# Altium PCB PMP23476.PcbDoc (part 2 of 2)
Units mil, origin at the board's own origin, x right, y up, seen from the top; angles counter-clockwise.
Board outline 965 x 1259.84 mil, 4 copper layers (Top Layer, Signal Layer 1, Signal Layer 2, Bottom Layer), stack 62 mil thick; 45 components, 25 nets, 111 pads, 20 vias.
Unrouted connection lines stored in the file: 2.
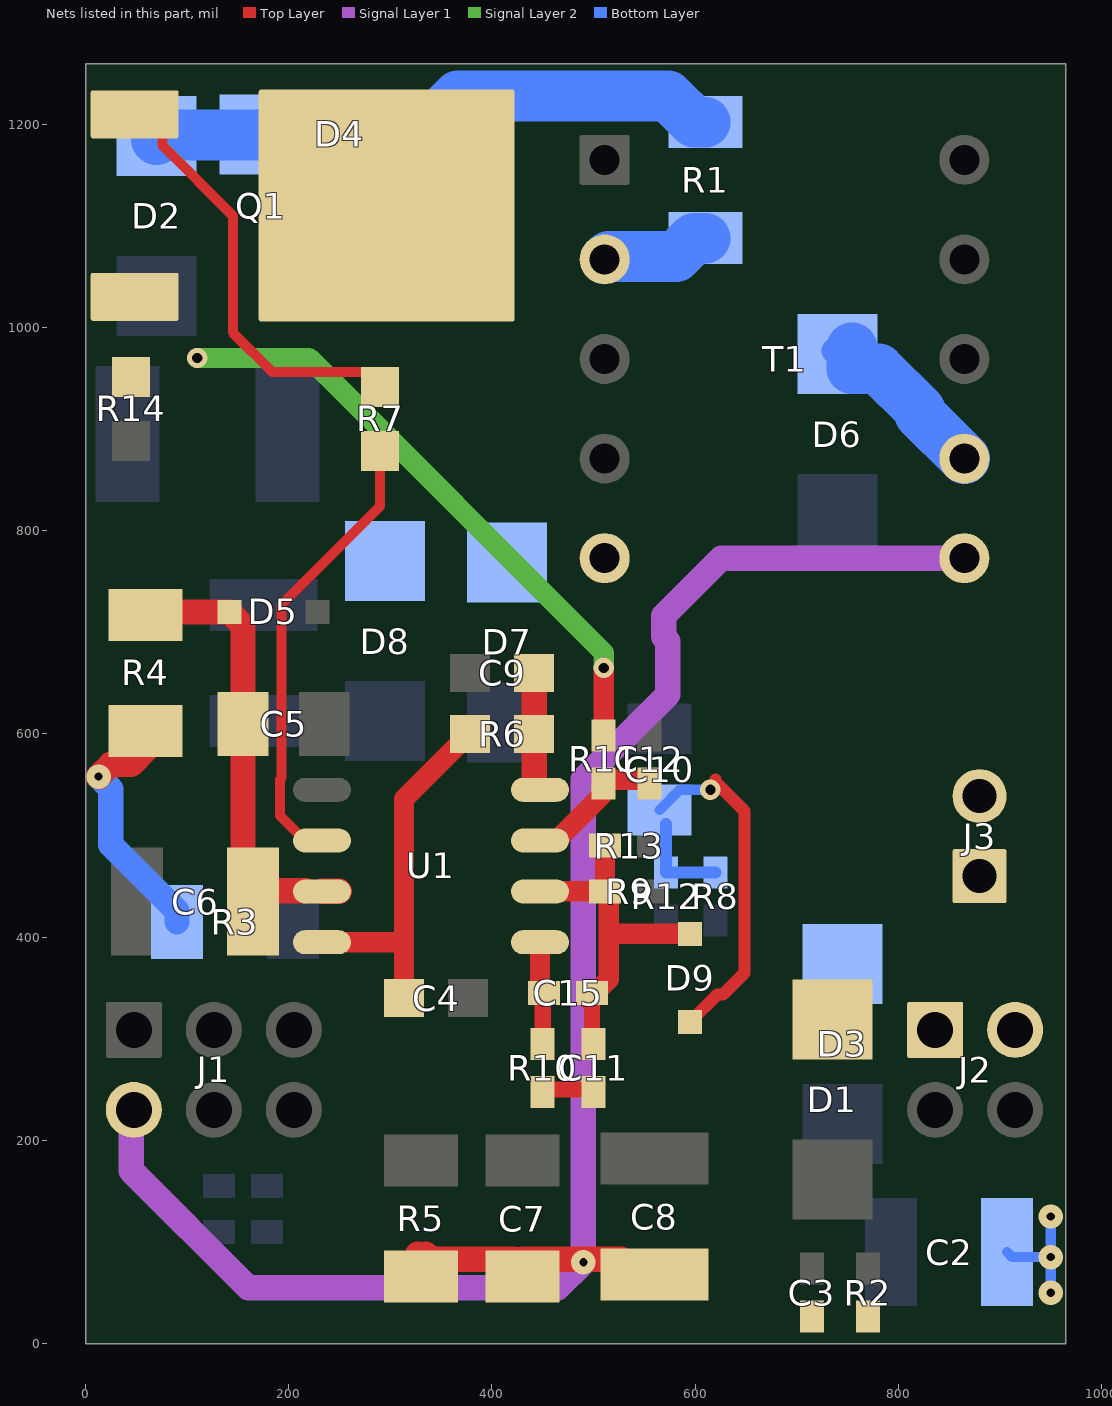
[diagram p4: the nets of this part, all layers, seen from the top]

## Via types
v1: diameter 24, hole 8, Top Layer to Bottom Layer, tented both sides, 12 vias
v2: diameter 20, hole 10, Top Layer to Bottom Layer, 8 vias

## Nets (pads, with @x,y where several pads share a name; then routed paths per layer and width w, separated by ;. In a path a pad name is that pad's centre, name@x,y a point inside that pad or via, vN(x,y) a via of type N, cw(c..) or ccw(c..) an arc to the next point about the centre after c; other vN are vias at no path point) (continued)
HSS: C7.2 C8.1 J1.2 R5.1 T1.6 | length 1788.8
  Top Layer w25: J1.2@45,230 J1.2@53.28,221.72 ; R5.1@327.09,87.91 R5.1@332.09,82.91 ; R5.1@330,82.91 R5.1@332.09,82.91 ; R5.1@335,80 R5.1@332.09,82.91 ; R5.1@335,87.91 R5.1@340,82.91 ; R5.1@348.09,74.82 R5.1@340,82.91 ; C7.2@425,80 422.09,82.91 R5.1@340,82.91 ; C7.2@430,82.91 527.09,82.91 C8.1@530,80 ; R5.1@332.09,82.91 R5.1@340,82.91
  Signal Layer 1 w25: J1.2@45,230 45,170 160,55 465,55 v1(490,80) ; v1@490,85 490,555.55 573.25,638.8 573.25,691.2 568.99,695.46 568.99,716.17 625.82,773 T1.6@865,773
NetC4_1: C4.1 R6.2 U1.8 | length 365.5
  Top Layer w20: U1.8@230,395 U1.8@232.72,395 310,395 ; C4.1@313.5,340 313.5,535.98 375,597.48 R6.2@375,600
NetC5_1: C5.1 C6.2 D5.1 R4.2 U1.7 | length 455
  Top Layer w25: R4.2@82.72,704 69.63,717.09 R4.2@58.8,717.09 61.71,720 D5.1@141.69,720 155,706.69 155,620 C5.1@160,615 ; C5.1@155,610 155,470 179.31,445.69 U1.7@216.67,445.69 ; U1.7@232.72,445 U1.7@250,445
NetC9_2: C9.2 R6.1 U1.4 | length 125.8
  Top Layer w25: U1.4@441.5,545.69 R6.1@441.5,605 ; C9.2@441.5,665 441.5,603.5 R6.1@445,600
NetC10_2: C10.2 D9.2 R8.1 R12.2 | length 430.2
  Top Layer w12: D9.2@595,316.69 621.96,343.65 627.41,343.65 648.56,364.8 648.56,524.18 620,552.74 620,555
  Bottom Layer w10: C10.2@565,525 585,545 v2(615,545)
  Bottom Layer w12: C10.2@571.46,511.46 R12.2@571.46,463.62 R8.1@620,463.62
NetC11_1: C11.1 R10.1 | length 50.9
  Top Layer w6: C11.1@497.76,250 C11.1@500,247.76
  Top Layer w16: R10.1@450,250 C11.1@497.76,250
NetC11_2: C11.2 C15.2 D9.1 R9.1 R13.2 U1.2 | length 357.7
  Top Layer w6: C11.2@498.62,296.38 C11.2@500,295 ; C15.2@498.62,344.37 C15.2@498.62,345
  Top Layer w16: C11.2@498.62,296.38 C15.2@498.62,344.37
  Top Layer w20: U1.2@447.28,445 R9.1@511.38,445 513.19,445 515,443.19 515,403.31 ; C15.2@495,338.62 495,342.56 496.81,344.37 498.62,344.37 500.75,344.37 515,358.62 515,403.31 ; R13.2@511.38,490 511.38,446.81 R9.1@511.59,446.59 ; D9.1@595,403.31 515,403.31
NetC12_1: C12.1 R11.1 U1.3 | length 125.5
  Top Layer w20: U1.3@447.28,495 463.54,495 508.19,539.65 R11.1@508.19,548.19 ; R11.1@520,555 553.19,555 555,553.19 C12.1@555,551.38
NetC15_1: C15.1 R10.2 U1.1 | length 100
  Top Layer w16: R10.2@450,295 C15.1@450,345
  Top Layer w20: C15.1@447.28,345 U1.1@447.28,395
NetD1_2: D1.2 D3.2 J3.1
NetD2_1: D2.1 D4.1 | length 103.3
  Bottom Layer w50: D2.1@70,1185 74.37,1189.37 170.63,1189.37 D4.1@171.26,1190
NetD4_2: D4.2 R1.1 | length 318.9
  Bottom Layer w20: D4.2@328.74,1190 335,1196.26 D4.2@358.74,1220
  Bottom Layer w50: D4.2@335,1185 D4.2@335,1196.26 ; D4.2@358.74,1220 366.61,1227.87 573.39,1227.87 599.17,1202.09 R1.1@610,1202.09
NetD6_2: D6.2 T1.7 | length 179.1
  Bottom Layer w25: D6.2@736.74,977 D6.2@740,973.74 ; D6.2@745,970 D6.2@748,973
  Bottom Layer w50: D6.2@754.37,980 754.37,959.37 780.63,959.37 821.36,918.64 821.36,914.64 T1.7@865,871
NetD7_2: D7.2 D8.2 T1.5
NetQ1_1: Q1.1 R7.2 | length 414.2
  Top Layer w10: Q1.1@65,1208.31 75.87,1197.43 75.87,1179.13 145,1110 145,995 183.82,956.18 276.3,956.18 290,942.48 R7.2@290,941.5
NetQ1_3: Q1.3 R11.2 R14.2 | length 601.5
  Top Layer w20: R11.2@510,598.62 v2(510,665)
  Signal Layer 2 w20: v2(110,970) 220,970 510,680 v2(510,665)
NetQ1_4: Q1.4 R1.2 T1.2 | length 102.4
  Bottom Layer w50: T1.2@515,1070 581.26,1070 599.17,1087.91 R1.2@610,1087.91
NetR3_2: R3.2 R4.1 | length 233.1
  Top Layer w25: v1(12.92,557.92) 25,570 45,570 R4.1@60,585
  Bottom Layer w25: v1(12.92,557.92) 25,545.83 25,490.83 90,425.83 R3.2@90,415
NetR7_1: R7.1 U1.6 | length 432.8
  Top Layer w10: U1.6@232.72,495 215.98,495 191.3,519.68 191.3,555.22 192.87,556.8 192.87,727.13 290,824.25 R7.1@290,860
SGND: C2.2 C3.2 J2.1 J2.3 J3.2 R2.1 | length 120
  Bottom Layer w10: C2.2@907.09,90 912.09,85 v1(950,85) ; v1(950,50) v1(950,85) ; v1(950,125) v1(950,85)
pads on no net: T1.3 T1.8 T1.9 T1.10
copper on no net: | length 121162.2
  Top Layer w1: 3666.62,2042.82 3766.3,2142.5 3886.3,2262.5 4006.3,2382.5 4126.3,2502.5 4246.3,2622.5 4366.3,2742.5 4486.3,2862.5 4606.3,2982.5 4726.3,3102.5 4786.3,3162.5 ; 3666.62,2102.82 3706.3,2142.5 3826.3,2262.5 3946.3,2382.5 4066.3,2502.5 4186.3,2622.5 4306.3,2742.5 4426.3,2862.5 4546.3,2982.5 4666.3,3102.5 4786.3,3222.5 ; 3666.62,2162.82 3766.3,2262.5 3886.3,2382.5 4006.3,2502.5 4126.3,2622.5 4246.3,2742.5 4366.3,2862.5 4486.3,2982.5 4606.3,3102.5 4726.3,3222.5 4786.3,3282.5 ; 3666.62,2222.82 3706.3,2262.5 3826.3,2382.5 3946.3,2502.5 4066.3,2622.5 4186.3,2742.5 4306.3,2862.5 4426.3,2982.5 4546.3,3102.5 4666.3,3222.5 4786.3,3342.5 ; 3666.62,2282.82 3766.3,2382.5 3886.3,2502.5 4006.3,2622.5 4126.3,2742.5 4246.3,2862.5 4366.3,2982.5 4486.3,3102.5 4606.3,3222.5 4726.3,3342.5 4786.3,3402.5 ; 3666.62,2342.82 3706.3,2382.5 3826.3,2502.5 3946.3,2622.5 4066.3,2742.5 4186.3,2862.5 4306.3,2982.5 4426.3,3102.5 4546.3,3222.5 4666.3,3342.5 4786.3,3462.5 ; 3666.62,2402.82 3766.3,2502.5 3886.3,2622.5 4006.3,2742.5 4126.3,2862.5 4246.3,2982.5 4366.3,3102.5 4486.3,3222.5 4606.3,3342.5 4726.3,3462.5 4786.3,3522.5 ; 3666.62,2462.82 3706.3,2502.5 3826.3,2622.5 3946.3,2742.5 4066.3,2862.5 4186.3,2982.5 4306.3,3102.5 4426.3,3222.5 4546.3,3342.5 4666.3,3462.5 4786.3,3582.5 ; 3666.62,2522.82 3766.3,2622.5 3886.3,2742.5 4006.3,2862.5 4126.3,2982.5 4246.3,3102.5 4366.3,3222.5 4486.3,3342.5 4606.3,3462.5 4726.3,3582.5 ; 3666.62,2582.82 3706.3,2622.5 3826.3,2742.5 3946.3,2862.5 4066.3,2982.5 4186.3,3102.5 4306.3,3222.5 4426.3,3342.5 4546.3,3462.5 4666.3,3582.5 ; 3666.62,2642.82 3766.3,2742.5 3886.3,2862.5 4006.3,2982.5 4126.3,3102.5 4246.3,3222.5 4366.3,3342.5 4486.3,3462.5 4606.3,3582.5 ; 3666.62,2702.82 3706.3,2742.5 3826.3,2862.5 3946.3,2982.5 4066.3,3102.5 4186.3,3222.5 4306.3,3342.5 4426.3,3462.5 4546.3,3582.5 ; 3666.62,2762.82 3766.3,2862.5 3886.3,2982.5 4006.3,3102.5 4126.3,3222.5 4246.3,3342.5 4366.3,3462.5 4486.3,3582.5 ; 3666.62,2822.82 3706.3,2862.5 3826.3,2982.5 3946.3,3102.5 4066.3,3222.5 4186.3,3342.5 4306.3,3462.5 4426.3,3582.5 ; 3666.62,2882.82 3766.3,2982.5 3886.3,3102.5 4006.3,3222.5 4126.3,3342.5 4246.3,3462.5 4366.3,3582.5 ; 3666.62,2942.82 3706.3,2982.5 3826.3,3102.5 3946.3,3222.5 4066.3,3342.5 4186.3,3462.5 4306.3,3582.5 ; 3666.62,3002.82 3766.3,3102.5 3886.3,3222.5 4006.3,3342.5 4126.3,3462.5 4246.3,3582.5 ; 3666.62,3062.82 3706.3,3102.5 3826.3,3222.5 3946.3,3342.5 4066.3,3462.5 4186.3,3582.5 ; 3666.62,3122.82 3766.3,3222.5 3886.3,3342.5 4006.3,3462.5 4126.3,3582.5 ; 3666.62,3182.82 3706.3,3222.5 3826.3,3342.5 3946.3,3462.5 4066.3,3582.5 ; 3666.62,3242.82 3766.3,3342.5 3886.3,3462.5 4006.3,3582.5 ; 3666.62,3302.82 3706.3,3342.5 3826.3,3462.5 3946.3,3582.5 ; 3666.62,3362.82 3766.3,3462.5 3886.3,3582.5 ; 3666.62,3422.82 3706.3,3462.5 3826.3,3582.5 ; 3666.62,3482.82 3766.3,3582.5 ; 3666.62,3542.82 3706.3,3582.5 ; 3706.3,2022.5 3826.3,2142.5 3946.3,2262.5 4066.3,2382.5 4186.3,2502.5 4306.3,2622.5 4426.3,2742.5 4546.3,2862.5 4666.3,2982.5 4786.3,3102.5 ; 3766.3,2022.5 3886.3,2142.5 4006.3,2262.5 4126.3,2382.5 4246.3,2502.5 4366.3,2622.5 4486.3,2742.5 4606.3,2862.5 4726.3,2982.5 4786.3,3042.5 ; 3826.3,2022.5 3946.3,2142.5 4066.3,2262.5 4186.3,2382.5 4306.3,2502.5 4426.3,2622.5 4546.3,2742.5 4666.3,2862.5 4786.3,2982.5 ; 3886.3,2022.5 4006.3,2142.5 4126.3,2262.5 4246.3,2382.5 4366.3,2502.5 4486.3,2622.5 4606.3,2742.5 4726.3,2862.5 4786.3,2922.5 ; 3946.3,2022.5 4066.3,2142.5 4186.3,2262.5 4306.3,2382.5 4426.3,2502.5 4546.3,2622.5 4666.3,2742.5 4786.3,2862.5 ; 4006.3,2022.5 4126.3,2142.5 4246.3,2262.5 4366.3,2382.5 4486.3,2502.5 4606.3,2622.5 4726.3,2742.5 4786.3,2802.5 ; 4066.3,2022.5 4186.3,2142.5 4306.3,2262.5 4426.3,2382.5 4546.3,2502.5 4666.3,2622.5 4786.3,2742.5 ; 4126.3,2022.5 4246.3,2142.5 4366.3,2262.5 4486.3,2382.5 4606.3,2502.5 4726.3,2622.5 4786.3,2682.5 ; 4186.3,2022.5 4306.3,2142.5 4426.3,2262.5 4546.3,2382.5 4666.3,2502.5 4786.3,2622.5 ; 4246.3,2022.5 4366.3,2142.5 4486.3,2262.5 4606.3,2382.5 4726.3,2502.5 4786.3,2562.5 ; 4306.3,2022.5 4426.3,2142.5 4546.3,2262.5 4666.3,2382.5 4786.3,2502.5 ; 4366.3,2022.5 4486.3,2142.5 4606.3,2262.5 4726.3,2382.5 4786.3,2442.5 ; 4426.3,2022.5 4546.3,2142.5 4666.3,2262.5 4786.3,2382.5 ; 4486.3,2022.5 4606.3,2142.5 4726.3,2262.5 4786.3,2322.5 ; 4546.3,2022.5 4666.3,2142.5 4786.3,2262.5 ; 4606.3,2022.5 4726.3,2142.5 4786.3,2202.5 ; 4666.3,2022.5 4786.3,2142.5 ; 4726.3,2022.5 4786.3,2082.5
  Top Layer w15: 237.5,2142.5 647.41,2142.5 1587.15,2142.5 2446.92,2142.5 3096.76,2142.5 3666.62,2142.5 4786.3,2142.5 ; 237.5,2262.5 647.41,2262.5 1587.15,2262.5 2446.92,2262.5 3096.76,2262.5 3666.62,2262.5 4786.3,2262.5 ; 237.5,2382.5 647.41,2382.5 1587.15,2382.5 2446.92,2382.5 3096.76,2382.5 3666.62,2382.5 4786.3,2382.5 ; 237.5,2502.5 647.41,2502.5 1587.15,2502.5 2446.92,2502.5 3096.76,2502.5 3666.62,2502.5 4786.3,2502.5 ; 237.5,2622.5 647.41,2622.5 1587.15,2622.5 2446.92,2622.5 3096.76,2622.5 3666.62,2622.5 4786.3,2622.5 ; 237.5,2742.5 647.41,2742.5 1587.15,2742.5 2446.92,2742.5 3096.76,2742.5 3666.62,2742.5 4786.3,2742.5 ; 237.5,2862.5 647.41,2862.5 1587.15,2862.5 2446.92,2862.5 3096.76,2862.5 3666.62,2862.5 4786.3,2862.5 ; 237.5,2982.5 647.41,2982.5 1587.15,2982.5 2446.92,2982.5 3096.76,2982.5 3666.62,2982.5 4786.3,2982.5 ; 237.5,3102.5 647.41,3102.5 1587.15,3102.5 2446.92,3102.5 3096.76,3102.5 3666.62,3102.5 4786.3,3102.5 ; 237.5,3222.5 647.41,3222.5 1587.15,3222.5 2446.92,3222.5 3096.76,3222.5 3666.62,3222.5 4786.3,3222.5 ; 237.5,3342.5 647.41,3342.5 1587.15,3342.5 2446.92,3342.5 3096.76,3342.5 3666.62,3342.5 4786.3,3342.5 ; 237.5,3462.5 647.41,3462.5 1587.15,3462.5 2446.92,3462.5 3096.76,3462.5 3666.62,3462.5 4786.3,3462.5 ; 237.5,3582.5 4786.3,3582.5 ; 647.41,3702.5 647.41,2022.5 ; 1587.15,3702.5 1587.15,2022.5 ; 2446.92,3702.5 2446.92,2022.5 ; 3096.76,3702.5 3096.76,2022.5 ; 3666.62,3702.5 3666.62,2022.5 ; 647.41,2022.5 237.5,2022.5 237.5,3702.5 4786.3,3702.5 4786.3,2022.5 3666.62,2022.5 ; 647.41,2022.5 1587.15,2022.5 ; 1587.15,2022.5 2446.92,2022.5 ; 2446.92,2022.5 3096.76,2022.5 ; 3096.76,2022.5 3666.62,2022.5

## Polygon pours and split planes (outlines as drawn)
GND_PRI on Signal Layer 1 "SIGNAL_LAYER_1_GND_PRI_P108" (solid, remove dead copper, pour order 108): 5,1005 605,1005 655,955 655,295 360,0 0,0
SGND on Signal Layer 1 "SIGNAL_LAYER_1_SGND_P098" (solid, remove dead copper, pour order 98): 690,695 690,0 965,0 965,695
GND_PRI on Signal Layer 2 "SIGNAL_LAYER_2_GND_PRI_P111" (solid, remove dead copper, pour order 111): 275,831.62 275,165 545,165 660,280 660,581.62
GND_PRI on Signal Layer 2 "SIGNAL_LAYER_2_GND_PRI_P110" (solid, remove dead copper, pour order 110): 595,900 655,840 655,505 600,505 330,775 220,775 220,885 235,900
GND_PRI on Signal Layer 2 "SIGNAL_LAYER_2_GND_PRI_P109" (solid, remove dead copper, pour order 109): 0,950 210,950 265,895 265,165 0,165
SGND on Signal Layer 2 "SIGNAL_LAYER_2_SGND_P099" (solid, remove dead copper, pour order 99): 690,695 690,0 965,0 965,695
NetQ1_4 on Top Layer "TOP_LAYER_NETQ1_4_P105" (solid, remove dead copper, pour order 105): 165,1260 165,1005 175,995 510,995 555,1040 555,1105 535,1125 485,1125 465,1145 465,1260
GND_PRI on Top Layer "TOP_LAYER_GND_PRI_P104" (solid, remove dead copper, pour order 104): -5,1010 0,1005 600,1005 660,945 660,335 490,165 0.03,165
NetQ1_3 on Top Layer "TOP_LAYER_NETQ1_3_P100" (solid, remove dead copper, pour order 100): 0,1080 145,1080 145,945 120,920 0,920
SGND on Top Layer "TOP_LAYER_SGND_P094" (solid, remove dead copper, pour order 94): 690,695 690,0 965,0 965,695
NetD1_2 on Top Layer "TOP_LAYER_NETD1_2_P093" (solid, remove dead copper, pour order 93): 690,385 805,500 960,500 960,400 945,385 830,385 795,350 795,270 690,270
12Vs on Top Layer "TOP_LAYER_12VS_P091" (solid, remove dead copper, pour order 91): 690,60 695,55 860,55 860,155 880,175 965,175 965,265 810,265 800,255 800,200 785,185 695,185 690,180
GND_PRI on Bottom Layer "BOTTOM_LAYER_GND_PRI_P107" (solid, remove dead copper, pour order 107): 10,995 605,995 660,940 660,305 365,10 0,10
12Vp on Bottom Layer "BOTTOM_LAYER_12VP_P106" (solid, remove dead copper, pour order 106): 155,225 155,80 165,70 295,70 385,160 385,625 255,625 250,630 250,320
GND_PRI on Bottom Layer "BOTTOM_LAYER_GND_PRI_P103" (solid, remove dead copper, pour order 103): 95,700 110,685 230,685 250,705 250,970 225,995 120,995 95,970
12Vp on Bottom Layer "BOTTOM_LAYER_12VP_P102" (solid, remove dead copper, pour order 102): 115,575 130,560 555,560 570,575 630,575 645,590 645,645 630,660 125,660 120,655 115,655
NetD7_2 on Bottom Layer "BOTTOM_LAYER_NETD7_2_P101" (solid, remove dead copper, pour order 101): 250,815 540,815 565,790 565,725 545,705 265,705 250,720
SGND on Bottom Layer "BOTTOM_LAYER_SGND_P097" (solid, remove dead copper, pour order 97): 690,695 690,0 970,0 970,685 960,695
12Vs on Bottom Layer "BOTTOM_LAYER_12VS_P096" (solid, remove dead copper, pour order 96): 690,25 715,0 835,0 855,20 855,145 885,175 965,175 965,270 690,270
NetD1_2 on Bottom Layer "BOTTOM_LAYER_NETD1_2_P095" (solid, remove dead copper, pour order 95): 690,290 785,290 800,305 800,355 835,390 955,390 965,400 965,500 790,500 690,400

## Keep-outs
Keep-Out Layer:
  text ".Layer_Name" at 577,-858.49 h60

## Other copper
Top Layer:
  text "Layer" at 307.5,3612.5 h60
  text "Name" at 717.41,3612.5 h60
  text "Material" at 1657.15,3612.5 h60
  text "Thickness" at 2516.92,3612.5 h60
  text "Constant" at 3166.76,3612.5 h60
  text "Board Layer Stack" at 3736.62,3612.5 h60
  text "Top Overlay" at 717.41,3492.5 h60
  text "Top Solder" at 717.41,3372.5 h60
  text "Solder Resist" at 1657.15,3372.5 h60
  text "0.40mil" at 2516.92,3372.5 h60
  text "3.5" at 3166.76,3372.5 h60
  text "1" at 307.5,3252.5 h60
  text "Top Layer" at 717.41,3252.5 h60
  text "1.40mil" at 2516.92,3252.5 h60
  text "Dielectric 1" at 717.41,3132.5 h60
  text "8.00mil" at 2516.92,3132.5 h60
  text "4.2" at 3166.76,3132.5 h60
  text "Dielectric1" at 717.41,3012.5 h60
  text "8.00mil" at 2516.92,3012.5 h60
  text "4.2" at 3166.76,3012.5 h60
  text "2" at 307.5,2892.5 h60
  text "Signal Layer 1" at 717.41,2892.5 h60
  text "1.40mil" at 2516.92,2892.5 h60
  text "Dielectric 3" at 717.41,2772.5 h60
  text "FR-4" at 1657.15,2772.5 h60
  text "24.40mil" at 2516.92,2772.5 h60
  text "4.2" at 3166.76,2772.5 h60
  text "3" at 307.5,2652.5 h60
  text "Signal Layer 2" at 717.41,2652.5 h60
  text "1.40mil" at 2516.92,2652.5 h60
  text "Dielectric 2" at 717.41,2532.5 h60
  text "8.00mil" at 2516.92,2532.5 h60
  text "4.2" at 3166.76,2532.5 h60
  text "Dielectric 4" at 717.41,2412.5 h60
  text "8.00mil" at 2516.92,2412.5 h60
  text "4.2" at 3166.76,2412.5 h60
  text "4" at 307.5,2292.5 h60
  text "Bottom Layer" at 717.41,2292.5 h60
  text "1.40mil" at 2516.92,2292.5 h60
  text "Bottom Solder" at 717.41,2172.5 h60
  text "Solder Resist" at 1657.15,2172.5 h60
  text "0.40mil" at 2516.92,2172.5 h60
  text "3.5" at 3166.76,2172.5 h60
  text "Bottom Overlay" at 717.41,2052.5 h60
  text ".Layer_Name" at 577,-858.49 h60
Bottom Layer:
  text ".Layer_Name" at 577,-858.49 h60

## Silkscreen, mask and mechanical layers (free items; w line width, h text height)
Top Overlay:
  lines w10: 285,725 285,840 355,840 430,765 430,695 350,695 330,715 295,715 285,725
  text ".Layer_Name" at 577,-858.49 h60
Bottom Overlay:
  text "'.PRJ_Number'.PCB_Rev-" at 635,20 h60
  text ".Layer_Name" at 577,-858.49 h60
Top Paste:
  text ".Layer_Name" at 577,-858.49 h60
Bottom Paste:
  text ".Layer_Name" at 577,-858.49 h60
Top Solder:
  text ".Layer_Name" at 577,-858.49 h60
  text ".Layer_Name" at 577,-858.49 h60
Bottom Solder:
  text ".Layer_Name" at 577,-858.49 h60
Drill Guide:
  text ".Layer_Name" at 577,-858.49 h60
M1 Board Outline:
  lines w7: 0,0 0,1262.95 ; 0,1259.84 964.57,1259.84
  lines w10: 0,0 969.57,0 ; 964.57,1259.84 965,0
  text ".Layer_Name" at 577,-858.49 h60
M2 Board Dimensions:
  rectangle: 0,-275 125,-150
  rectangle: 125,-400 500,-275
  lines w7: 0,-275 1000,-275 ; 125,-400 125,-150 ; 250,-400 250,-150 ; 500,-400 500,-150 ; 750,-400 750,-150 ; 0,-400 1000,-400 1000,-150 0,-150 0,-400
  text ".Layer_Name" at 577,-858.49 h60
M3 3D STEP Top:
  text ".Layer_Name" at 577,-858.49 h60
M4 3D STEP Bottom:
  text ".Layer_Name" at 577,-858.49 h60
M5 Assembly Top:
  lines w10: -292,-930.17 6308,-930.17 ; -292,-726.83 6310,-726.83 ; -292,-523.5 -292,-1133.5 3713,-1133.5 6310,-1133.5 6310,-523.5 -291.5,-523.5 -291.5,-1133.5 1284,-1133.5 ; 2173,-1133.5 2173,-523.5 ; 3440,-726.83 3440,-523.5 ; 4280,-726.83 4280,-523.5 ; 4902,-1140 4902,-937.17
  text "COMPONENTS MARKED 'DNP' SHOULD NOT BE POPULATED." at 1153.5,-318.5 h60
  text "ASSEMBLY VARIANT:" at 1153,-434 h60
  text ".VariantName" at 2189,-434 h60
  text "PCB VIEWED FROM TOP SIDE" at -228.5,-655.67 h60
  text "BOARD #:" at 2248,-655.67 h60
  text ".PRJ_Number" at 2793.5,-655.67 h60
  text "REV:" at 3638,-655.67 h60
  text ".PCB_Rev" at 3929.5,-655.67 h60
  text "SVN REV:" at 4476,-655.67 h60
  text ".VersionControl_RevNumber" at 4982,-655.67 h60
  text "TID #:" at 2248,-859 h60
  text ".TID" at 2793.5,-859 h60
  text "PLOT NAME =" at -228.5,-1064.34 h60
  text ".plot_File_Name" at 577,-1064.34 h60
  text "GENERATED    :" at 2250,-1064.34 h60
  text ".Print_Date" at 3119.5,-1064.34 h60
  text ".Print_Time" at 3848.5,-1064.34 h60
  text "TEXAS INSTRUMENTS" at 5113,-1064.34 h60
M6 Assembly Bottom:
  lines w10: -292.5,-727.33 6309.5,-727.33 ; -290.5,-930.67 6309.5,-930.67 ; 1115.5,-1140.5 1115.5,-937.67 ; 1737.5,-727.33 1737.5,-524 ; 2577.5,-727.33 2577.5,-524 ; 3844.5,-1134 3844.5,-524 ; 4733.5,-1134 6309,-1134 6309,-524 -292.5,-524 -292.5,-1134 2304.5,-1134 6309.5,-1134 6309.5,-524
  text "COMPONENTS MARKED 'DNP' SHOULD NOT BE POPULATED." at 6102,-318 h60
  text ".VariantName" at 5058,-434 h60
  text "ASSEMBLY VARIANT:" at 6097,-434 h60
  text ".VersionControl_RevNumber" at 1035.5,-656.17 h60
  text "SVN REV:" at 1541.5,-656.17 h60
  text ".PCB_Rev" at 2088,-656.17 h60
  text "REV:" at 2379.5,-656.17 h60
  text ".PRJ_Number" at 3224,-656.17 h60
  text "BOARD #:" at 3769.5,-656.17 h60
  text "PCB VIEWED FROM BOTTOM SIDE" at 6246,-656.17 h60
  text ".TID" at 3224,-859.5 h60
  text "TID #:" at 3769.5,-859.5 h60
  text "TEXAS INSTRUMENTS" at 904.5,-1064.84 h60
  text ".Print_Time" at 2169,-1064.84 h60
  text ".Print_Date" at 2898,-1064.84 h60
  text "GENERATED    :" at 3767.5,-1064.84 h60
  text ".plot_File_Name" at 5440.5,-1064.84 h60
  text "PLOT NAME =" at 6246,-1064.84 h60
M9 Title Sheet:
  drawing of 57 lines, arcs and shapes, not listed
  text "1" at 739.84,8036.5 h70
  text "2" at 3235.5,8036.5 h70
  text "3" at 5724.84,8036.5 h70
  text "4" at 8231.51,8036.5 h70
  text "5" at 10730.5,8036.5 h70
  text "6" at 13235.5,8036.5 h70
  text "A" at -416.5,6893.5 h70
  text "A" at 14383.5,6893.5 h70
  text "B" at -416.5,4513.5 h70
  text "B" at 14383.5,4513.5 h70
  text "C" at -416.5,2138.5 h70
  text "C" at 14383.5,2138.5 h70
  text "PROJECT TITLE:" at 11343.5,277.5 h45
  text ".PRJ_Title" at 11393.5,144.17 h70
  text "DESIGNED FOR:" at 11343.5,-23.5 h45
  text ".PRJ_Customer" at 11393.5,-163.5 h70
  text "D" at -416.5,-231.5 h70
  text "D" at 14383.5,-231.5 h70
  text "FILE NAME:" at 11343.5,-323.5 h45
  text ".PCB_File_Name_No_Path" at 11393.5,-443.5 h70
  text "Texas Instruments (TI) and/or its licensors do not warrant the accuracy or completeness of this specification" at 6374,-605.34 h45
  text "ENGINEER:" at 11343.5,-613.5 h45
  text "LAYOUT BY:" at 12848.5,-613.5 h45
  text "or any information contained therein. TI and/or its licensors do not warrant that this design will meet" at 6329.01,-718 h45
  text ".PRJ_Engineer" at 11393.5,-768.49 h70
  text ".PCB_Layout" at 12899,-768.49 h70
  text "the specifications, will be suitable for your application or fit for any particular purpose, or will operate in" at 6329.01,-830.67 h45
  text ".Layer_Name" at 577,-858.49 h60
  text "ALTIUM DESIGNER VERSION:" at 12848.5,-923.5 h45
  text "an implementation. TI and/or its licensors do not warrant that the design is production worthy. You should" at 6329.01,-943.33 h45
  text "completely validate and test your design implementation to confirm the system functionality for your application." at 6374,-1056 h45
  text ".print_Scale" at 11393.5,-1056.83 h70
  text ".Application_BuildNumber" at 12899,-1056.83 h70
  text "1" at 739.84,-1263.5 h70
  text "2" at 3235.5,-1263.5 h70
  text "3" at 5724.84,-1263.5 h70
  text "4" at 8231.51,-1263.5 h70
  text "5" at 10730.5,-1263.5 h70
  text "6" at 13235.5,-1263.5 h70
M10 Fab Notes:
  drawing of 173 lines, arcs and shapes, not listed
  text "DESIGN INFORMATION" at 12378.02,6201 h60
  text "MIN. TRACK WIDTH:" at 11733.46,6021 h60
  text "10" at 12829.7,6021 h60
  text "MIL" at 12984.46,6021 h60
  text "MIN. CLEARANCE:" at 11733.46,5889 h60
  text "0.2" at 12769.7,5889 h60
  text "mm" at 12984.46,5889 h60
  text "MIN. VIA PAD SIZE:" at 11733.46,5757 h60
  text "20" at 12799.71,5757 h60
  text "MIL" at 12984.46,5757 h60
  text "0.05mm (2MIL)" at 12428.46,5615.29 h60
  text "MINIMUM ANNULAR RING" at 11404.23,5611 h60
  text "EXTERNAL" at 13136.46,5611 h60
  text "PER" at 11604.23,5493 h60
  text "IPC-D-275 CLASS 2 LEVEL C" at 11824.23,5493 h60
  text "MIL, HOLES" at 13312.46,5380.71 h60
  text "+/-" at 12920,5380 h60
  text "+/-" at 13774,5380 h60
  text "REGISTRATION TOLERANCES:" at 11404.23,5375 h60
  text "METAL" at 12604,5375 h60
  text "5" at 13180.2,5375 h60
  text "3" at 14013.2,5375 h60
  text "MIL" at 14129.46,5375 h60
  text "+/-" at 13774,5262 h60
  text "HOLE SIZE TOLERANCE (UNLESS OTHERWISE SPECIFIED):" at 11404.23,5257 h60
  text "3" at 14013.2,5257 h60
  text "MIL" at 14129.46,5257 h60
  text "MATERIAL:" at 11329.46,5047.54 h60
  text "FR-4 High Tg" at 12315.9,4907.21 h60
  text "FR-408" at 11750.46,4898.64 h60
  text "OTHER" at 13238.46,4898.64 h60
  text "X" at 12161,4895 h60
  text "62 MIL (1.6mm) +/-10%" at 12070.56,4735.92 h60
  text "THICKNESS:" at 11404.23,4731.64 h60
  text "X" at 11942.4,4731.64 h60
  text "OTHER" at 13355.46,4731.64 h60
  text "TOLERANCE:" at 11404.23,4573.64 h60
  text "X" at 12243.53,4573.64 h60
  text "ANSI IPC-6012 TYPE 3 CLASS 2" at 12430.48,4573.64 h60
  text "OTHER +/-" at 12430.46,4417.64 h60
  text "BOW & TWIST:" at 11404.23,4260.64 h60
  text "X" at 12243.53,4260.64 h60
  text "ANSI IPC-6012 TYPE 3 CLASS 2" at 12430.48,4260.64 h60
  text "OTHER +/-" at 12430.46,4102.13 h60
  text "DRILLING:" at 11329.46,3963.64 h60
  text "REFERENCE:" at 11404.23,3846.64 h60
  text "X" at 12052.46,3846.64 h60
  text "AS SHOWN" at 12239.46,3846.64 h60
  text "X" at 12953.46,3846.64 h60
  text "NC_DRILL FILES" at 13090.46,3846.64 h60
  text "PTH COPPER THICKNESS:" at 11404.23,3688.64 h60
  text "X" at 12534.46,3688.64 h60
  text "20-30 um" at 12671.46,3688.64 h60
  text "OTHER" at 13388.46,3688.64 h60
  text "BOARD FINISH:" at 11329.46,3529.64 h60
  text "SILKSCREEN:" at 11484.68,3411.64 h60
  text "X" at 12433.46,3411.64 h60
  text "TOP" at 12559.46,3411.64 h60
  text "X" at 12943.46,3411.64 h60
  text "BOTTOM" at 13070.46,3411.64 h60
  text "SILKSCREEN COLOR:" at 11484.68,3244.64 h60
  text "X" at 12432.42,3244.64 h60
  text "WHITE" at 12559.46,3244.64 h60
  text "OTHER" at 13070.46,3244.64 h60
  text "X" at 12563.42,3085.44 h60
  text "GREEN" at 12690.46,3085.44 h60
  text "OTHER" at 13308.46,3085.44 h60
  text "SOLDER RESIST COLOR:" at 11484.68,3074.64 h60
  text "X" at 12563.42,2915.44 h60
  text "MATTE" at 12690.46,2915.44 h60
  text "SEMI-GLOSS" at 13308,2914.8 h60
  text "IMMERSION GOLD (ENIG)" at 12390.46,2726.92 h60
  text "ENEPIG" at 13728,2723.64 h60
  text "SURFACE FINISH:" at 11329.46,2722.64 h60
  text "X" at 12203.51,2722.64 h60
  text "IMM. TIN/SILVER OR EQUIV" at 11659,2565.64 h60
  text "OTHER" at 13090.46,2565.64 h60
  text "ARRAY/PANEL:" at 11329.46,2386.64 h60
  text "CUT AND TRIM PER M1 BOARD OUTLINE" at 12390.46,2382.35 h60
  text "N.C. ROUTE" at 12390.46,2230.64 h60
  text "X" at 13069.46,2230.64 h60
  text "V. SCORE" at 13256.46,2230.64 h60
  text "CERTIFICATION:" at 11329.46,2093.64 h60
  text "MATERIALS AND WORKMANSHIP FOR ALL PCBS" at 12054.46,2093.64 h60
  text "TO MEET OR EXCEED THE REQUIREMENTS OF:" at 12054.46,1995.64 h60
  text "X" at 11680.96,1859.13 h60
  text "ANSI IPC-A-600F CLASS ->" at 11819.96,1859.13 h60
  text "X" at 13459.02,1859.13 h60
  text "2" at 13577.96,1859.14 h60
  text "1" at 13262.96,1857.64 h60
  text "3" at 13931.96,1857.64 h60
  text "X" at 12495.02,1699.64 h60
  text "RoHS" at 12631.96,1699.64 h60
  text "OTHER" at 13276.36,1699.64 h60
  text "PER ORDER" at 13673.42,1699.64 h60
  text "ALL BOARDS MUST MEET OR EXCEED UL94-V0 REQUIREMENTS." at 11357,1534 h60
  text "PCB MUST BEAR THE UL94V-0 UL REGISTERED MATERIAL ID NUMBER" at 11357,1414 h60
  text "ADDITIONAL REQUIREMENTS:" at 11329.46,1240.64 h60
  text "MICROSECTION:" at 11404.23,1125.64 h60
  text "YES" at 12309.96,1125.64 h60
  text "X" at 13050,970 h60
  text "REQUIRED" at 13171.46,969.49 h60
  text "BARE BOARD ELEC. TEST:" at 11404.23,966.64 h60
  text "NONE" at 12709.96,966.64 h60
  text "PER ORDER" at 13763.46,966.64 h60
  text ".Layer_Name" at 577,-858.49 h60
M11 Gerber Information:
  lines w10: -292,-930.17 6308,-930.17 ; -292,-726.83 6310,-726.83 ; -292,-523.5 -292,-1133.5 3713,-1133.5 6310,-1133.5 6310,-523.5 -291.5,-523.5 -291.5,-1133.5 1284,-1133.5 ; 2173,-1133.5 2173,-523.5 ; 3440,-726.83 3440,-523.5 ; 4280,-726.83 4280,-523.5 ; 4902,-1140 4902,-937.17
  text "ALL ARTWORK VIEWED FROM TOP SIDE" at -228.5,-655.67 h60
  text "BOARD #:" at 2248,-655.67 h60
  text ".PRJ_Number" at 2793.5,-655.67 h60
  text "REV:" at 3638,-655.67 h60
  text ".PCB_Rev" at 3929.5,-655.67 h60
  text "SVN REV:" at 4476,-655.67 h60
  text ".VersionControl_RevNumber" at 4982,-655.67 h60
  text "LAYER NAME =" at -228.5,-858.49 h60
  text "TID #:" at 2248,-859 h60
  text ".TID" at 2793.5,-859 h60
  text "PLOT NAME =" at -228.5,-1064.34 h60
  text ".plot_File_Name" at 577,-1064.34 h60
  text "GENERATED    :" at 2250,-1064.34 h60
  text ".Print_Date" at 3119.5,-1064.34 h60
  text ".Print_Time" at 3848.5,-1064.34 h60
  text "TEXAS INSTRUMENTS" at 5113,-1064.34 h60
M12 Stackup:
  text ".Layer_Name" at 577,-858.49 h60
M13 Component Bodies Top:
  text ".Layer_Name" at 577,-858.49 h60
M14 Component Bodies Bottom:
  text ".Layer_Name" at 577,-858.49 h60
M15 Courtyards Top:
  text ".Layer_Name" at 577,-858.49 h60
M16 Courtyards Bottom:
  text ".Layer_Name" at 577,-858.49 h60
Drill Drawing:
  circle w10: c5443.72,3413.2 r27.63
  lines w10: 5416.09,3012.62 5471.34,3012.62 5471.34,3067.87 5416.09,3067.87 5416.09,3012.62 ; 5416.09,3192.19 5471.34,3192.19 5443.72,3136.94 5416.09,3192.19 ; 5416.09,3275.07 5429.9,3275.07 5443.72,3261.26 5457.53,3275.07 5471.34,3275.07 5457.53,3288.88 5471.34,3302.7 5457.53,3302.7 5443.72,3316.51 5429.9,3302.7 5416.09,3302.7 5429.9,3288.88 5416.09,3275.07 ; 5416.09,3509.9 5443.72,3523.71 5471.34,3509.9 5457.53,3537.52 5471.34,3565.15 5443.72,3551.34 5416.09,3565.15 5429.9,3537.52 5416.09,3509.9
  lines w12: 5366,2975.32 8463.7,2975.32 ; 5366,3596.92 8463.7,3596.92 ; 5703.86,2851 5703.86,3721.24 ; 5976.64,2851 5976.64,3721.24 ; 6538.64,2851 6538.64,3721.24 ; 6797.78,2851 6797.78,3721.24 ; 7172.94,2851 7172.94,3721.24 ; 7897.27,2851 7897.27,3721.24 ; 5366,2851 8463.7,2851 8463.7,3721.24 5366,3721.24 5366,2851
  text "Symbol" at 5440.59,3634.22 h72
  text "Count" at 5741.16,3634.22 h72
  text "Hole Size" at 6013.94,3634.22 h72
  text "Plated" at 6575.93,3634.22 h72
  text "Hole Type" at 6835.07,3634.22 h72
  text "Drill Layer Pair" at 7210.23,3634.22 h72
  text "Hole Tolerance" at 7934.56,3634.22 h72
  text "12" at 5741.16,3509.9 h60
  text "0.203mm (8.00mil)" at 6013.94,3509.9 h60
  text "PTH" at 6575.93,3509.9 h60
  text "Round" at 6835.07,3509.9 h60
  text "Top Layer - Bottom Layer" at 7210.23,3509.9 h60
  text "8" at 5741.16,3385.58 h60
  text "0.254mm (10.00mil)" at 6013.94,3385.58 h60
  text "PTH" at 6575.93,3385.58 h60
  text "Round" at 6835.07,3385.58 h60
  text "Top Layer - Bottom Layer" at 7210.23,3385.58 h60
  text "10" at 5741.16,3261.26 h60
  text "0.750mm (29.53mil)" at 6013.94,3261.26 h60
  text "PTH" at 6575.93,3261.26 h60
  text "Round" at 6835.07,3261.26 h60
  text "Top Layer - Bottom Layer" at 7210.23,3261.26 h60
  text "2" at 5741.16,3136.94 h60
  text "0.850mm (33.47mil)" at 6013.94,3136.94 h60
  text "PTH" at 6575.93,3136.94 h60
  text "Round" at 6835.07,3136.94 h60
  text "Top Layer - Bottom Layer" at 7210.23,3136.94 h60
  text "10" at 5741.16,3012.62 h60
  text "0.900mm (35.43mil)" at 6013.94,3012.62 h60
  text "PTH" at 6575.93,3012.62 h60
  text "Round" at 6835.07,3012.62 h60
  text "Top Layer - Bottom Layer" at 7210.23,3012.62 h60
  text "42 Total" at 5741.16,2888.3 h60
  text ".Layer_Name" at 577,-858.49 h60
M17 Embedded Cavity:
  text ".Layer_Name" at 577,-858.49 h60
M18 Embedded Assembly:
  text ".Layer_Name" at 577,-858.49 h60
M19 Embedded Keepout:
  text ".Layer_Name" at 577,-858.49 h60

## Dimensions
0,-400 to 1000,-400 on M2 Board Dimensions
0,0 to 0,1259.84 on M2 Board Dimensions
0,0 to 965,0 on M2 Board Dimensions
